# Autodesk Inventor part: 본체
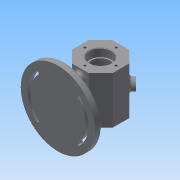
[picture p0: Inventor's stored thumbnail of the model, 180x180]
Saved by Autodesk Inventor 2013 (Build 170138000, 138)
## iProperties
Created: 2017-06
Part Number: 본체
Material: 일반
Document SubType Name: Modeling
Designer: Administrator
Density: 1 g/cm^3
Author: Administrator
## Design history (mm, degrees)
sketch "스케치2" dims "d0" = 60
  geometry: L1 (12.426, 30)-(30, 12.426); L2 (30, 12.426)-(30, -12.426); L3 (30, -12.426)-(12.426, -30); L4 (12.426, -30)-(-12.426, -30); L5 (-12.426, -30)-(-30, -12.426); L6 (-30, -12.426)-(-30, 12.426); L7 (-30, 12.426)-(-12.426, 30); L8 (-12.426, 30)-(12.426, 30); L9 (0, 0)-(12.426, 30); L10 (0, 30)-(0, 0); 3 further points
  constraints: 20 end point, 3 coincident, 1 midpoint, 1 perpendicular, 1 vertical alignment, 19 other
extrude "돌출1" new body sketch "스케치2" stored distance "d2" = 70; taper "d3" = 0 deg
sketch "스케치3"
  geometry: L1 (30, -35)-(-30, -35) reference; L2 (-30, -35)-(-30, 35) reference; L3 (-30, 35)-(30, 35) reference; L4 (30, 35)-(30, -35) reference; L5 (16, 35)-(16, 23.3); L6 (15.7, 23)-(14, 23); L7 (14, 23)-(14, 20); L8 (14, 20)-(22, 20); L9 (25, 17)-(25, -17) reference; L10 (22, -20)-(14, -20); L11 (14, -20)-(14, -23); L12 (14, -23)-(15.7, -23); L13 (16, -23.3)-(16, -35); L14 (0, 44.777)-(0, -45.565); L15 (16, 35)-(0, 35); L16 (16, -35)-(0, -35); L17 (16, -35)-(0, -35); A1 r 3 centre (22, -17) between (22, -20) and (25, -17); A2 r 3 centre (22, 17) between (25, 17) and (22, 20); A3 r 0.3 centre (15.7, 23.3) between (15.7, 23) and (16, 23.3); A4 r 0.3 centre (15.7, -23.3) between (16, -23.3) and (15.7, -23); 4 further points
  constraints: 26 end point, 8 point on circle, 8 point on line, 8 tangent, 6 parallel, 4 centre point, 3 midpoint, 2 collinear, 2 equal radius, 2 perpendicular, 2 vertical
  dimensions: "d5" = 32 diameter of L5 L14; "d7" = 28 diameter of L7 L14; "d8" = 50 diameter of L9 L14; "d9" = 40 distance between parallel lines of L10 L8; "d10" = 28 diameter of L11 L14; "d11" = 32 diameter of L13 L14; "d12" = 12 distance of L5.start point (16, 23); "d13" = 12 distance of point (16, -23) L13.end; "d14" = 3 radius of A1; "d16" = 0.3 radius of A3
revolve "회전1" sketch "스케치3" stored, may be unused: angle "d15" = 90 deg
node "작업 평면1"
sketch "스케치4"
  geometry: L1 (0, 0)-(69.994, 0); L2 (0, 0)-(-72.326, 0); C1 r 55 at (0, 0); A1 r 48 centre (0, 0) between (-33.941, 33.941) and (-33.941, -33.941); A2 r 48 centre (0, 0) between (33.941, -33.941) and (33.941, 33.941); A3 r 38 centre (0, 0) between (26.87, -26.87) and (26.87, 26.87); A4 r 38 centre (0, 0) between (-26.87, 26.87) and (-26.87, -26.87); A5 r 5 centre (-30.406, 30.406) between (-26.87, 26.87) and (-33.941, 33.941); A6 r 5 centre (-30.406, -30.406) between (-33.941, -33.941) and (-26.87, -26.87); A7 r 5 centre (30.406, 30.406) between (33.941, 33.941) and (26.87, 26.87); A8 r 5 centre (30.406, -30.406) between (26.87, -26.87) and (33.941, -33.941); A9 r 45 centre (0, 0) between (31.82, -31.82) and (31.82, 31.82); A10 r 2 centre (30.406, -30.406) between (28.991, -28.991) and (31.82, -31.82); A11 r 41 centre (0, 0) between (28.991, -28.991) and (28.991, 28.991); A12 r 2 centre (30.406, 30.406) between (31.82, 31.82) and (28.991, 28.991); A13 r 41 centre (0, 0) between (-28.991, 28.991) and (-28.991, -28.991); A14 r 2 centre (-30.406, 30.406) between (-28.991, 28.991) and (-31.82, 31.82); A15 r 45 centre (0, 0) between (-31.82, 31.82) and (-31.82, -31.82); A16 r 2 centre (-30.406, -30.406) between (-31.82, -31.82) and (-28.991, -28.991); 1 further point
  constraints: 32 point on circle, 17 centre point, 4 end point, 4 tangent, 3 coincident, 1 collinear, 1 horizontal, 6 other
  dimensions: "d18" = 110 diameter of C1; "d26" = 5 radius of A8; "d27" = 5 radius of A6; "d28" = 48 radius of A2; "d29" = 48 radius of A1; "d30" = 38 radius of A4; "d31" = 38 radius of A3; "d32" = 5 radius of A7; "d33" = 5 radius of A5; "d35" = 30.40559 distance from line of L1 A7.centre; "d39" = 30.40559 distance from line of L1 A8.centre; "d40" = 30.40559 distance from line of L2 A6.centre; "d41" = 30.40559 distance from line of L2 A5.centre; "d42" = 3 radial gap between concentric circles of A2 A9; "d43" = 3 radial gap between concentric circles of A4 A13
extrude "돌출2" join sketch "스케치4" distance "d44" = 10; taper "d45" = 0 deg
extrude "돌출4" join sketch "스케치4" distance "d48" = 7; taper "d49" = 0 deg
sketch "스케치5"
  geometry: L1 (5, -24)-(-5, -24); L2 (-5, -24)-(-5, 24); L3 (-5, 24)-(5, 24); L4 (5, 24)-(5, -24); L5 (5, -24)-(-5, 24); L6 (-5, -24)-(5, 24); A1 r 5 centre (0, -24) between (-5, -24) and (5, -24); A2 r 5 centre (0, 24) between (5, 24) and (-5, 24); 1 further point
  constraints: 12 end point, 4 midpoint, 4 point on circle, 2 centre point, 2 parallel, 1 horizontal, 1 perpendicular
  dimensions: "d50" = 48 distance of L2.end L1.end; "d52" = 10 distance of L2.end L3.end
extrude "돌출5" join sketch "스케치5" stored distance "d53" = 7; taper "d54" = 0 deg
sketch "스케치6"
  geometry: C1 r 8 at (-12.426, 35); C2 r 4 at (-12.426, 35); 1 further point
  constraints: 2 centre point, 2 coincident
  dimensions: "d55" = 16 diameter of C1; "d57" = 8 diameter of C2
extrude "돌출6" join sketch "스케치6" distance "d58" = 7; taper "d59" = 0 deg
extrude "돌출7" cut sketch "스케치6" distance "d60" = 20; taper "d61" = 0 deg
fillet "모깎기1" dims "d62" = 1, "d63" = 5, "d64" = 3
chamfer "모따기1" distance "d65" = 1; stored, may be unused: second distance "d66" = 2, angle "d67" = 45 deg
sketch "스케치7"
  geometry: L1 (-17.695, 0)-(-17.695, 70) reference; L2 (24.024, 0)-(0, 0) reference; 2 further points
  constraints: 1 other
  dimensions: "d68" = 30 distance from line of L1 point (12.305, 35); "d69" = 35 distance from line of L2 point (12.305, 35)
feature "엠보싱1" sketch "스케치7" dims "d0" = 60, "d5" = 32, "d7" = 28, "d8" = 50, "d9" = 40, "d10" = 28, "d11" = 32, "d12" = 12, "d13" = 12, "d14" = 3, "d16" = 0.3, "d70" = 0.5, "d71" = 0
sketch "스케치8"
  geometry: C1 r 3.058 at (0, 23); C2 r 3.198 at (23, 0); C3 r 6.035 at (0, -23); C4 r 5.01 at (-23, 0); A1 r 23 centre (0, 0) between (0, 23) and (23, 0); 1 further point
  constraints: 5 centre point, 4 point on circle, 1 coincident
  dimensions: "d72" = 46 diameter of A1
hole "구멍1" sketch "스케치8" at (23, 0), (0, -23), (-23, 0), (0, 23) diameter "d73" = 3.242; stored, may be unused: countersink angle "d77" = 90 deg, drill point angle "d79" = 118 deg; dims "d74" = 8, "d75" = 4, "d76" = 2, "d78" = 10
sketch "스케치9"
  geometry: C1 r 2.28 at (0, 23); C2 r 4.459 at (23, 0); C3 r 3.895 at (0, -23); C4 r 4.752 at (-23, 0); A1 r 23 centre (0, 0) between (0, 23) and (23, 0); 1 further point
  constraints: 5 centre point, 4 point on circle, 1 coincident
  dimensions: "d80" = 46 diameter of A1
hole "구멍2" sketch "스케치9" at (0, 23), (-23, 0), (0, -23), (23, 0) diameter "d81" = 3.242; stored, may be unused: countersink angle "d85" = 90 deg, drill point angle "d87" = 118 deg; dims "d82" = 8, "d83" = 4, "d84" = 2, "d86" = 10
node "솔리드1"
node "절단 모서리 투영1"
other parameters: "d17" = -63, "d20" = 45 deg, "d22" = 45 deg, "d24" = 76, "d25" = 96
